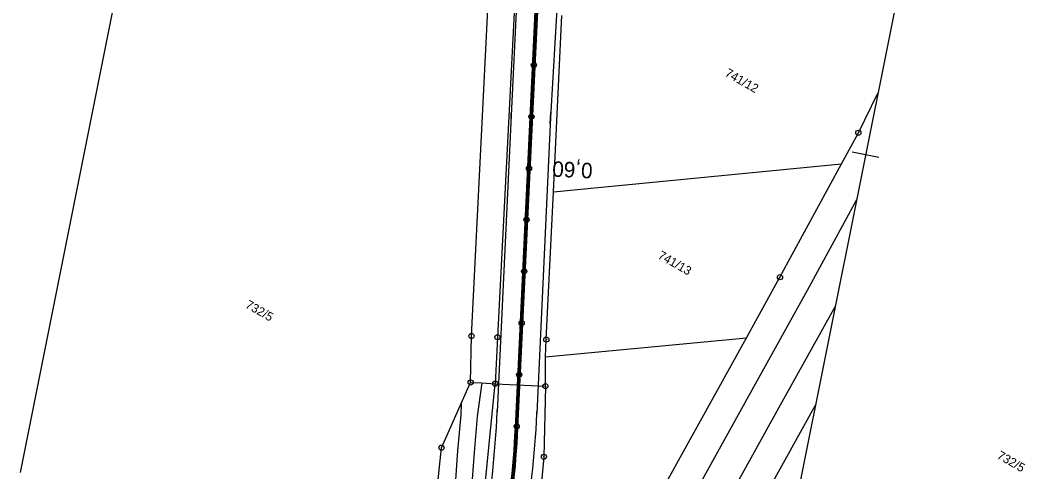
# Model space of a CAD drawing. Extents: x -548552 to -543113, y -1131925 to -1123599.
# Drawn here: x -548371.9 to -548176.7, y -1131261.1 to -1131173.6 of the extents above; entities that cross this region are included whole.
import ezdxf

# ---------------------------------------------------------------- set-up
doc = ezdxf.new("R2010")
doc.units = 0
for name, color, linetype in [('Hranice parcel', 7, 'Continuous'), ('Parcelní čísla', 7, 'Continuous'), ('Profile', 7, 'Continuous'), ('PROFILY NÁVRH', 7, 'Continuous'), ('STANIČENÍ', 7, 'Continuous'), ('Vnitřní kresba', 7, 'Continuous'), ('Značky bodu BP', 7, 'Continuous')]:
    doc.layers.add(name, color=color, linetype=linetype)

msp = doc.modelspace()

# ---------------------------------------------------------------- linework, layer by layer
at = {"layer": 'Hranice parcel'}
for p, q in [((-548268.63, -1131206.89), (-548266.99, -1131172.73)), ((-548268.63, -1131206.89), (-548212.83, -1131201.45)), ((-548270.17, -1131238.81), (-548231.26, -1131235.12)), ((-548270.19, -1131244.48), (-548270.17, -1131238.81)), ((-548279.89, -1131244), (-548270.19, -1131244.48))]:
    msp.add_line(p, q, dxfattribs=at)
for points in [[(-548264.85, -1130945.08), (-548269.14, -1131030.91), (-548269.98, -1131050.17), (-548279.48, -1131235), (-548279.89, -1131244)], [(-548284.67, -1131243.76), (-548284.5, -1131234.77), (-548278.29, -1131110.83)], [(-548212.83, -1131201.45), (-548209.56, -1131195.44), (-548205.77, -1131187.78)], [(-548231.26, -1131235.12), (-548224.75, -1131223.39), (-548212.83, -1131201.45)], [(-548270.17, -1131238.81), (-548270.01, -1131235.46), (-548268.63, -1131206.89)], [(-548266.43, -1131298.79), (-548255.67, -1131279.15), (-548231.26, -1131235.12)], [(-548299.27, -1131302.15), (-548294.98, -1131287.64), (-548292.13, -1131273.62), (-548290.31, -1131256.39), (-548286.47, -1131247.81), (-548284.67, -1131243.76)], [(-548284.67, -1131243.76), (-548282.49, -1131243.86), (-548279.89, -1131244)], [(-548314.32, -1131392.63), (-548312.77, -1131383.54), (-548312.66, -1131382.92), (-548308.95, -1131361.27), (-548307.79, -1131357.27), (-548288.01, -1131297.23), (-548282.46, -1131269.31), (-548279.89, -1131244)], [(-548270.19, -1131244.48), (-548270.47, -1131258.15), (-548271.5, -1131269.23), (-548273.14, -1131299.44), (-548266.43, -1131298.79)], [(-548217.85, -1131248.08), (-548239.93, -1131287.89), (-548244.91, -1131296.98)]]:
    msp.add_lwpolyline(points, dxfattribs=at)
at = {"layer": 'Profile'}
for p, q in [((-548163.86, -1130978.72), (-548203.22, -1131175.07)), ((-548180.11, -1131059.78), (-548203.22, -1131175.07)), ((-548180.11, -1131059.78), (-548203.22, -1131175.07)), ((-548348.82, -1131145.88), (-548371.93, -1131261.16)), ((-548348.82, -1131145.88), (-548371.93, -1131261.16)), ((-548203.22, -1131175.07), (-548226.32, -1131290.35)), ((-548203.22, -1131175.07), (-548226.32, -1131290.35)), ((-548203.22, -1131175.07), (-548226.32, -1131290.35)), ((-548208.16, -1131199.73), (-548210.75, -1131199.21)), ((-548205.57, -1131200.25), (-548208.16, -1131199.73))]:
    msp.add_line(p, q, dxfattribs=at)
at = {"layer": 'PROFILY NÁVRH'}
for p, q in [((-548276, -1131252.52), (-548261.4, -1130945.78)), ((-548275.5, -1131252.55), (-548260.91, -1130945.87)), ((-548275.11, -1131157.13), (-548276.81, -1131192.09)), ((-548267.13, -1131157.51), (-548269.17, -1131192.46)), ((-548276.81, -1131192.09), (-548279.52, -1131249.42)), ((-548269.17, -1131192.46), (-548271.84, -1131249.79))]:
    msp.add_line(p, q, dxfattribs=at)
for centre, radius, start, end in [((-548486.15, -1131239.66), 206.86, 343.7664, 357.2955), ((-548461.61, -1131240.96), 189.98, 342.6152, 357.3354)]:
    msp.add_arc(centre, radius, start, end, dxfattribs=at)
for major_axis in [(4.76, 179.69), (4.77, 180.19)]:
    msp.add_ellipse((-548455.55, -1131243.98), major_axis=major_axis, ratio=0.999998, start_param=4.428044, end_param=4.691325, dxfattribs=at)
at = {"layer": 'STANIČENÍ'}
for p, q in [((-548275.75, -1131252.54), (-548261.16, -1130945.83)), ((-548276.84, -1131192.68), (-548276.79, -1131191.64)), ((-548269.23, -1131193.69), (-548269.12, -1131191.53)), ((-548279.54, -1131249.8), (-548279.5, -1131249.09)), ((-548271.86, -1131250.17), (-548271.82, -1131249.42))]:
    msp.add_line(p, q, dxfattribs=at)
for centre, radius in [((-548272.08, -1131175.3), 0.1), ((-548272.03, -1131174.3), 0.1), ((-548272.17, -1131177.3), 0.1), ((-548272.12, -1131176.3), 0.1), ((-548272.27, -1131179.3), 0.1), ((-548272.22, -1131178.3), 0.1), ((-548272.36, -1131181.29), 0.1), ((-548272.31, -1131180.3), 0.1), ((-548272.41, -1131182.31), 0.5), ((-548272.46, -1131183.29), 0.1), ((-548272.41, -1131182.29), 0.1), ((-548272.55, -1131185.29), 0.1), ((-548272.5, -1131184.29), 0.1), ((-548272.6, -1131186.29), 0.1), ((-548272.69, -1131188.29), 0.1), ((-548272.65, -1131187.29), 0.1), ((-548272.79, -1131190.28), 0.1), ((-548272.74, -1131189.29), 0.1), ((-548272.89, -1131192.3), 0.5), ((-548272.89, -1131192.28), 0.1), ((-548272.84, -1131191.28), 0.1), ((-548272.98, -1131194.28), 0.1), ((-548272.93, -1131193.28), 0.1), ((-548273.08, -1131196.28), 0.1), ((-548273.03, -1131195.28), 0.1), ((-548273.17, -1131198.28), 0.1), ((-548273.12, -1131197.28), 0.1), ((-548273.27, -1131200.27), 0.1), ((-548273.22, -1131199.28), 0.1), ((-548273.36, -1131202.29), 0.5), ((-548273.36, -1131202.27), 0.1), ((-548273.31, -1131201.27), 0.1), ((-548273.46, -1131204.27), 0.1), ((-548273.41, -1131203.27), 0.1), ((-548273.55, -1131206.27), 0.1), ((-548273.5, -1131205.27), 0.1), ((-548273.65, -1131208.27), 0.1), ((-548273.6, -1131207.27), 0.1), ((-548273.74, -1131210.26), 0.1), ((-548273.69, -1131209.26), 0.1), ((-548273.84, -1131212.28), 0.5), ((-548273.84, -1131212.26), 0.1), ((-548273.79, -1131211.26), 0.1), ((-548273.93, -1131214.26), 0.1), ((-548273.88, -1131213.26), 0.1), ((-548274.03, -1131216.26), 0.1), ((-548273.98, -1131215.26), 0.1), ((-548274.12, -1131218.25), 0.1), ((-548274.07, -1131217.26), 0.1), ((-548274.22, -1131220.25), 0.1), ((-548274.17, -1131219.25), 0.1), ((-548274.31, -1131222.26), 0.5), ((-548274.31, -1131222.25), 0.1), ((-548274.26, -1131221.25), 0.1), ((-548274.41, -1131224.25), 0.1), ((-548274.36, -1131223.25), 0.1), ((-548274.5, -1131226.25), 0.1), ((-548274.45, -1131225.25), 0.1), ((-548274.6, -1131228.24), 0.1), ((-548274.55, -1131227.24), 0.1), ((-548274.64, -1131229.24), 0.1), ((-548274.79, -1131232.25), 0.5), ((-548274.74, -1131231.24), 0.1), ((-548274.69, -1131230.24), 0.1), ((-548274.83, -1131233.24), 0.1), ((-548274.79, -1131232.24), 0.1), ((-548274.93, -1131235.24), 0.1), ((-548274.88, -1131234.24), 0.1), ((-548275.02, -1131237.23), 0.1), ((-548274.98, -1131236.24), 0.1), ((-548275.12, -1131239.23), 0.1), ((-548275.07, -1131238.23), 0.1), ((-548275.26, -1131242.24), 0.5), ((-548275.21, -1131241.23), 0.1), ((-548275.17, -1131240.23), 0.1), ((-548275.31, -1131243.23), 0.1), ((-548275.26, -1131242.23), 0.1), ((-548275.4, -1131245.23), 0.1), ((-548275.36, -1131244.23), 0.1), ((-548275.5, -1131247.22), 0.1), ((-548275.45, -1131246.22), 0.1), ((-548275.59, -1131249.22), 0.1), ((-548275.55, -1131248.22), 0.1), ((-548275.69, -1131251.22), 0.1), ((-548275.64, -1131250.22), 0.1), ((-548275.74, -1131252.23), 0.5), ((-548275.79, -1131253.22), 0.1), ((-548275.74, -1131252.22), 0.1), ((-548275.9, -1131255.21), 0.1), ((-548275.84, -1131254.22), 0.1), ((-548276.04, -1131257.21), 0.1), ((-548275.96, -1131256.21), 0.1), ((-548276.19, -1131259.2), 0.1), ((-548276.11, -1131258.21), 0.1), ((-548276.28, -1131260.2), 0.1)]:
    msp.add_circle(centre, radius, dxfattribs=at)
msp.add_ellipse((-548455.55, -1131243.98), major_axis=(4.77, 179.94), ratio=0.999998, start_param=4.428044, end_param=4.691325, dxfattribs=at)
at = {"layer": 'Vnitřní kresba'}
for points in [[(-548209.9, -1131208.42), (-548219.45, -1131225.95), (-548230.23, -1131245.26), (-548241.15, -1131265.07), (-548251.32, -1131283.44)], [(-548214.01, -1131228.9), (-548224.68, -1131248.19), (-548235.73, -1131268.11), (-548245.86, -1131286.31)], [(-548282.49, -1131243.86), (-548283.4, -1131250.37), (-548284.01, -1131257.33)], [(-548286.47, -1131247.81), (-548286.54, -1131250), (-548287.18, -1131257.02)], [(-548287.18, -1131257.02), (-548287.9, -1131267.29), (-548288.69, -1131274.24), (-548291.46, -1131287.57), (-548293.7, -1131296.39), (-548296.81, -1131306.77)], [(-548284.01, -1131257.33), (-548284.74, -1131267.64), (-548285.41, -1131274.83), (-548288.35, -1131288.29), (-548290.59, -1131297.28), (-548293.7, -1131307.84)]]:
    msp.add_lwpolyline(points, dxfattribs=at)
at = {"layer": 'Značky bodu BP'}
for centre, radius in [((-548209.56, -1131195.44), 0.5), ((-548209.56, -1131195.44), 0.0303), ((-548224.75, -1131223.39), 0.5), ((-548224.75, -1131223.39), 0.0303), ((-548284.5, -1131234.77), 0.5), ((-548284.5, -1131234.77), 0.0303), ((-548279.48, -1131235), 0.5), ((-548279.48, -1131235), 0.0303), ((-548270.01, -1131235.46), 0.5), ((-548270.01, -1131235.46), 0.0303), ((-548284.67, -1131243.76), 0.5), ((-548284.67, -1131243.76), 0.0303), ((-548279.89, -1131244), 0.5), ((-548279.89, -1131244), 0.0303), ((-548270.19, -1131244.48), 0.5), ((-548270.19, -1131244.48), 0.0303), ((-548290.31, -1131256.39), 0.5), ((-548290.31, -1131256.39), 0.0303), ((-548270.47, -1131258.15), 0.5), ((-548270.47, -1131258.15), 0.0303)]:
    msp.add_circle(centre, radius, dxfattribs=at)

# ---------------------------------------------------------------- texts
at = {"layer": 'Parcelní čísla'}
for s, p in [('741/12', (-548235.57, -1131184.34)), ('741/13', (-548248.55, -1131219.64)), ('732/5', (-548328.45, -1131229.19)), ('732/5', (-548182.85, -1131258.37))]:
    msp.add_text(s, height=1.7, rotation=330.1814, dxfattribs=at).set_placement(p)
at = {"layer": 'STANIČENÍ'}
msp.add_text('0,60', height=3, rotation=177.2755, dxfattribs=at).set_placement((-548260.97, -1131201.29))

doc.saveas('drawing.dxf')
